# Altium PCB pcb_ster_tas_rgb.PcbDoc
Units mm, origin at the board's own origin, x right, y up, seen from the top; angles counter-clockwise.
Board outline 73.41 x 11.43 mm, 2 copper layers (Top Layer, Bottom Layer); 22 components, 12 nets, 52 pads, 17 vias.
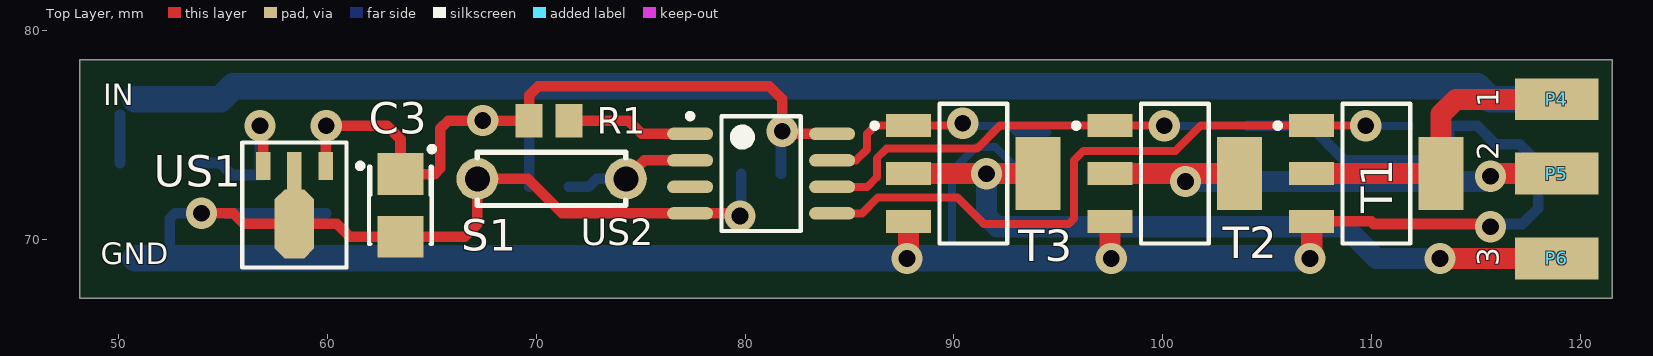
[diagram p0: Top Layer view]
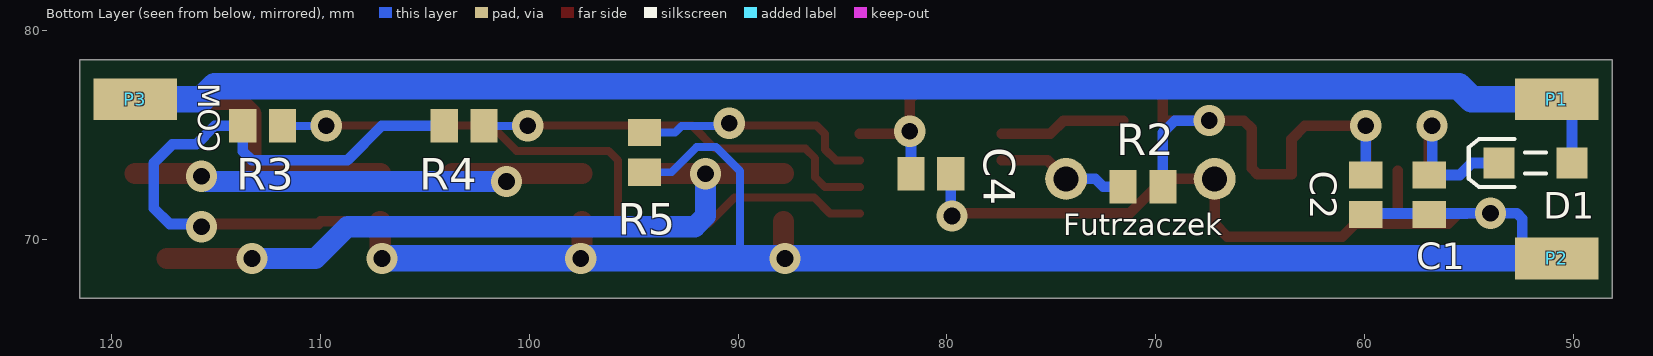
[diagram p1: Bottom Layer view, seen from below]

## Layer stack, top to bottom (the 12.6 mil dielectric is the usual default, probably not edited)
Top Layer: signal copper 0.0356
Dielectric: dielectric 0.32, FR-4, Dk 4.8
Bottom Layer: signal copper 0.0356

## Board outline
48.133,67.183 121.539,67.183 121.539,78.613 48.133,78.613

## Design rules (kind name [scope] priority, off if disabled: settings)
Clearance [All] p1: gap=0.254
PolygonConnect [All] p1: connectstyle=Relief reliefconductorwidth=0.254 reliefentries=4 polygonreliefangle="90 Angle"
RoutingVias [All] p1: holewidth=0.711 width=1.27 viastyle="Through Hole" minholewidth=0 minwidth=0 maxholewidth=7.112 maxwidth=12.7
SilkscreenOverComponentPads [All] p1: minsilkscreentomaskgap=0.254
SolderMaskExpansion [All] p1: expansion=0.102
Width [All] p1: maxlimit=2.54 minlimit=0.254 preferedwidth=0.254
27 further rules are at their usual default settings.

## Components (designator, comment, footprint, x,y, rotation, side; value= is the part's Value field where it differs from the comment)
C1 "100n" MELF-0805 56.896,72.136 r90 bottom
C2 "100n" MELF-0805 59.944,72.136 r90 bottom
C3 "22u/16V B" "Tantal B 3528-1411" 63.5,71.628 r270 top
C4 "100p" MELF-0805 80.772,73.152 r0 bottom
D1 "1N4148" "dioda MINIMELF" 51.816,73.66 r0 bottom
P1 "IN" "Pad SMD 2x4mm" 50.8,76.708 r180 bottom
P2 "GND" "Pad SMD 2x4mm" 50.8,69.088 r180 bottom
P3 "COM" "Pad SMD 2x4mm" 118.872,76.708 r180 bottom
P4 "1" "Pad SMD 2x4mm" 118.872,76.708 r0 top
P5 "2" "Pad SMD 2x4mm" 118.872,73.152 r0 top
P6 "3" "Pad SMD 2x4mm" 118.872,69.088 r0 top
R1 "10k" MELF-0805 70.612,75.692 r180 top
R2 "10k" MELF-0805 70.612,72.517 r180 bottom
R3 "10k" MELF-0805 112.776,75.438 r180 bottom
R4 "10k" MELF-0805 103.124,75.438 r180 bottom
R5 "10k" MELF-0805 94.488,74.168 r90 bottom
S1 "switch 3x6" "tact switch 3x6" 70.739,72.898 r0 top
T1 "IRLL014N" SOT-223 110.236,73.152 r270 top
T2 "IRLL014N" SOT-223 100.584,73.152 r270 top
T3 "IRLL014N" SOT-223 90.932,73.152 r270 top
US1 "78L05" PK03 58.42,72.136 r180 top
US2 "ATtiny25" 8S2_N 80.772,73.152 r0 top

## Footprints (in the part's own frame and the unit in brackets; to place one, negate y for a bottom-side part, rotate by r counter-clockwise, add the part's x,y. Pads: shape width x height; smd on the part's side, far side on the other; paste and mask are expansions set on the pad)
8S2_N [mm] "SOP, 8-Leads, Body 5.3x5.3mm, Pitch 1.27mm, IPC Medium Density"
  oval 2.2x0.6 smd: 1(-3.4,1.905) 2(-3.4,0.635) 3(-3.4,-0.635) 4(-3.4,-1.905) 5(3.4,-1.905) 6(3.4,-0.635) 7(3.4,0.635) 8(3.4,1.905)
  silkscreen extent -3.52,-2.75 1.9,2.88, body extent -2.73,-2.75 2.73,2.75, height 2.03
"dioda MINIMELF" [mm] "SMT LED; 2 Flat Leads"
  rect 1.5x1.5 smd: 1(-1.75,0) 2(1.75,0)
  silkscreen extent -0.5,-1.15 3.2,1.15
MELF-0805 [mm] "Metal Electrode Face (MELF) Resistor; Body 2 x 1.4 mm (LxDia)"
  rect 1.3x1.6 smd: 1(-0.95,0) 2(0.95,0)
"Pad SMD 2x4mm" [mm]
  rect 4x2 smd: 1(0,0)
PK03 [mm] "SOT-89; Body 4.6 x 4.25 mm, inc. leads (LxW max)"
  oct 1.9x3.3 smd: 0(0,1.388)
  rect 0.7x1.35 smd: 1(-1.5,-1.388) 3(1.5,-1.388)
  rect 0.7x1.8 smd: 2(0,-1.162)
  silkscreen extent -3.28,-2.51 2.5,3.49
SOT-223 [mm] "SOT-223/SC-73; 4 Leads; Body 6.7 x 7.3 mm, inc. leads (LxW max)"
  rect 1.1x2.15 smd: 1(-2.3,-3.1) 2(0,-3.1) 3(2.3,-3.1)
  rect 3.5x2.15 smd: 4(0,3.1)
  silkscreen extent -3.35,-4.85 3.35,1.63
"tact switch 3x6" [mm]
  round 2 hole 1.2: 1(-3.556,0) 2(3.556,0)
  silkscreen extent -3.56,-1.27 3.56,1.27
"Tantal B 3528-1411" [mm] "Capacitor, SM Tantalum; Body 3.5 x 2.8 mm (LxW typ)"
  rect 2x2.2 smd: 1(-1.5,0) 2(1.5,0)
  silkscreen extent -2.82,-1.5 1.85,1.63, body extent -2.6,-1.2 2.6,1.2, height 2.5

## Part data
C1 C2 C4: library part kondensator
C3: library part "kond biegunowy", "Polarized Capacitor"
D1: library part Diode, "Default Diode"
P1 P2 P3 P4 P5 P6: library part Pad, "Pad"
R1 R2 R3 R4 R5: library part rezystor
S1: library part "switch pojed"
T1 T2 T3: "HEXFET Power MOSFET"
US1: library part µA78L05CPKR, "Positive-Voltage Regulator"
US2: library part ATtiny15L-1SC, "8-Bit AVR Microcontroller with 1K Byte of Flash Memory"

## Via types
v1: diameter 1.5, hole 0.8, Top Layer to Bottom Layer, 17 vias

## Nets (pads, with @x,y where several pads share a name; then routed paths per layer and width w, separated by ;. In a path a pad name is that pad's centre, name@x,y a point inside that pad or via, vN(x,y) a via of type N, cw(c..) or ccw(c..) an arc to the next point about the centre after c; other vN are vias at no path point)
NetC1_1: C1.1 C2.1 C3.2 C4.1 P2.1 R3.1 R4.1 R5.1 S1.1 T1.3 T2.3 T3.3 US1.0 US1.2 US2.4 | length 146.1
  Top Layer w0.508: v1(53.975,71.247) 55.499,71.247 55.998,70.748 US1.0 60.443,70.748 61.063,70.128 C3.2 66.572,70.128 67.183,70.739 S1.1 69.596,72.898 71.247,71.247 75.565,71.247 US2.4 79.629,71.247 v1(79.756,71.12) ; US1.0 US1.2 ; T1.3@107.15,70.866 109.982,70.866 110.109,70.739 115.57,70.739 v1(115.697,70.612)
  Top Layer w1.016: v1@87.832,69.163 T3.3 ; v1@97.484,69.14 T2.3 ; v1@107.136,69.163 T1.3
  Bottom Layer w0.381: 89.916,69.088 89.916,73.279 91.059,74.422 91.986,74.422 93.19,73.218 R5.1
  Bottom Layer w0.508: P2.1 50.927,69.215 52.451,69.215 52.451,70.993 52.705,71.247 v1(53.975,71.247) 55.118,71.247 55.121,71.244 56.896,71.244 C2.1@59.944,71.244 ; v1@79.822,71.313 C4.1 ; R4.1 107.061,75.438 108.712,73.787 113.284,73.787 113.726,74.229 R3.1 115.062,75.438 115.951,74.549 117.094,74.549 117.983,73.66 117.983,71.501 117.221,70.739 115.824,70.739 v1(115.697,70.612)
  Bottom Layer w1.27: P2.1 v1(87.757,69.088) 89.916,69.088 v1(97.536,69.088) v1(107.061,69.088)
NetC1_2: C1.2 D1.2 US1.3 | length 7.9
  Top Layer w0.508: v1(56.769,75.438) 56.92,75.287 US1.3
  Bottom Layer w0.508: D1.2 54.864,73.66 55.438,73.086 C1.2 56.769,73.213 v1(56.769,75.438)
NetC2_2: C2.2 C3.1 C4.2 R1.2 R2.2 US1.1 US2.8 | length 42.3
  Top Layer w0.508: US1.1 v1@59.92,75.414 ; v1(59.944,75.438) 62.865,75.438 63.5,74.803 C3.1 65.127,73.128 65.405,73.406 65.405,75.311 65.786,75.692 v1(67.437,75.692) R1.2 69.662,76.901 70.104,77.343 81.153,77.343 81.788,76.708 81.788,75.057 US2.8
  Bottom Layer w0.508: C2.2@59.944,73.536 v1(59.944,75.438) ; v1(67.437,75.692) 69.088,75.692 69.662,75.118 R2.2 ; C4.2 v1@81.722,74.991
  other v1: 81.788,75.184
NetD1_1: D1.1 P1.1 P3.1 | length 70.9
  Bottom Layer w0.508: D1.1 P1.1@50.066,75.974
  Bottom Layer w1.27: P1.1 54.864,76.708 55.487,77.331 115.074,77.331 115.697,76.708 P3.1
NetP4_1: P4.1 T1.2 T1.4 | length 14.9
  Top Layer w1.016: T1.2 T1.4 113.336,75.998 114.046,76.708 P4.1
NetP5_1: P5.1 T2.2 T2.4 | length 24
  Top Layer w1.016: T2.2 T2.4 ; v1@115.824,73.152 P5.1
  Bottom Layer w1.016: v1(101.092,72.771) 115.443,72.771 v1(115.697,73.025)
NetP6_1: P6.1 T3.2 T3.4 | length 34.9
  Top Layer w1.016: T3.2 T3.4 ; v1(113.284,69.088) P6.1@117.348,69.088
  Bottom Layer w1.016: v1(91.567,73.152) 91.567,71.12 92.075,70.612 108.712,70.612 110.236,69.088 v1(113.284,69.088)
NetR1_1: R1.1 US2.1 | length 6.1
  Top Layer w0.508: R1.1 74.422,75.692 75.057,75.057 US2.1
NetR2_1: R2.1 S1.2 US2.2 | length 6.3
  Top Layer w0.508: S1.2 75.184,73.787 US2.2
  Bottom Layer w0.508: R2.1 72.517,72.517 72.898,72.898 S1.2
NetR3_2: R3.2 T1.1 US2.5 | length 32.1
  Top Layer w0.381: US2.5 85.598,71.247 86.36,72.009 90.17,72.009 91.44,70.739 95.504,70.739 95.758,70.993 95.758,73.787 96.214,74.243 100.621,74.243 101.83,75.452 T1.1 v1@109.714,75.452
  Bottom Layer w0.381: v1(109.728,75.438) R3.2
NetR4_2: R4.2 T2.1 US2.6 | length 19.5
  Top Layer w0.381: US2.6 85.852,72.517 86.312,72.977 86.312,73.886 86.773,74.347 91.111,74.347 92.216,75.452 T2.1 v1@99.808,75.452
  Bottom Layer w0.381: v1(100.076,75.438) R4.2
NetR5_2: R5.2 T3.1 US2.7 | length 11.7
  Top Layer w0.381: US2.7 85.315,73.787 85.838,74.309 85.838,75.043 86.247,75.452 T3.1 v1@90.551,75.452
  Bottom Layer w0.381: v1(90.424,75.565) 90.551,75.438 92.71,75.438 93.03,75.118 R5.2
pads on no net: US2.3

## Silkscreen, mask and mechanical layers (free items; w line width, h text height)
Top Overlay:
  text "1" at 116.459,76.327 h1.78 r90
  text "IN" at 49.276,76.073 h1.78
  text "2" at 116.459,73.787 h1.78 r90
  text "3" at 116.459,68.707 h1.78 r90
  text "GND" at 49.149,68.453 h1.78
Bottom Overlay:
  text "COM" at 116.205,74.168 h1.78 r90
  text "Futrzaczek" at 74.422,69.85 h1.78
Mechanical 1:
  the board outline again, w0.508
